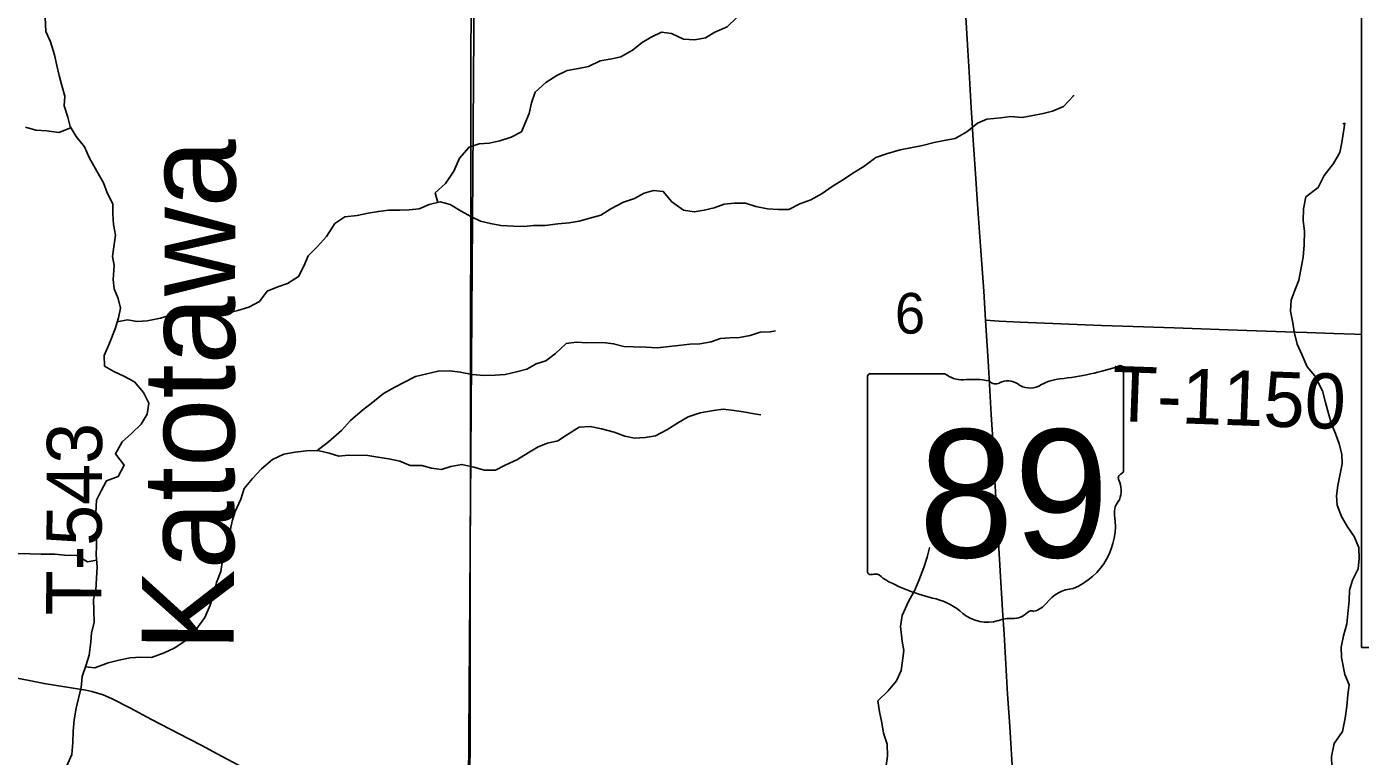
# Model space of a CAD drawing. Extents: x 0 to 34, y 0 to 22.
# Drawn here: x 2.753 to 4.127, y 15.888 to 16.64 of the extents above; entities that cross this region are included whole.
import ezdxf

# ---------------------------------------------------------------- set-up
doc = ezdxf.new("R2010")
doc.units = 0
for name, color, linetype in [('GM_X_Interstate_Route', 7, 'Continuous'), ('GM_X_Minor_River', 7, 'Continuous'), ('GM_X_Minor_River_Text', 7, 'Continuous'), ('GM_X_Section', 7, 'Continuous'), ('GM_X_Section_Text', 7, 'Continuous'), ('GM_X_State_Location', 7, 'Continuous'), ('GM_X_State_Route', 7, 'Continuous'), ('GM_X_State_Shield', 7, 'Continuous'), ('GM_X_Township_Road', 7, 'Continuous'), ('GM_X_Township_Road_Text', 7, 'Continuous')]:
    doc.layers.add(name, color=color, linetype=linetype)

msp = doc.modelspace()

# ---------------------------------------------------------------- linework, layer by layer
at = {"layer": 'GM_X_Interstate_Route'}
msp.add_lwpolyline([(2.1, 16.8784), (2.1, 14.1), (3.2011, 14.1), (3.2037, 14.7782), (3.2041, 14.9016), (3.2042, 14.9221), (3.2098, 15.7617), (3.2111, 16.7578), (3.2115, 16.8719), (3.0939, 16.8719), (2.6014, 16.878)], close=True, dxfattribs=at)
msp.add_lwpolyline([(4.6269, 16.8701), (3.6554, 16.8713), (3.6203, 16.8714), (3.2115, 16.8719), (3.2111, 16.7578), (3.2098, 15.7617), (3.2042, 14.9221), (3.2041, 14.9016), (3.2037, 14.7782), (3.2011, 14.1), (8.2568, 14.1)], dxfattribs=at)
at = {"layer": 'GM_X_Minor_River'}
for points in [[(2.7523, 16.7083), (2.7549, 16.6977), (2.7597, 16.6874), (2.7672, 16.6778), (2.7724, 16.6679), (2.7723, 16.6493), (2.7729, 16.6349), (2.7777, 16.6242), (2.7818, 16.6109), (2.7843, 16.5999)], [(3.1768, 16.4588), (3.174, 16.4686), (3.1847, 16.4783), (3.1931, 16.4908), (3.1989, 16.5044), (3.2089, 16.5157), (3.2191, 16.519), (3.2297, 16.52), (3.2407, 16.5222), (3.2521, 16.5259), (3.2628, 16.5314), (3.2709, 16.5503), (3.2732, 16.5613), (3.2771, 16.5723), (3.2878, 16.5824), (3.2992, 16.5895), (3.3099, 16.5947), (3.3216, 16.5969), (3.3319, 16.5987), (3.344, 16.6047), (3.3558, 16.6068), (3.3653, 16.609), (3.3771, 16.6157), (3.387, 16.6236), (3.3965, 16.6292), (3.4071, 16.6344), (3.4174, 16.6328), (3.4298, 16.627), (3.4415, 16.6265), (3.4525, 16.6283), (3.462, 16.6342), (3.4746, 16.6398), (3.4845, 16.6492)], [(2.7843, 16.5999), (2.7865, 16.5896), (2.7895, 16.5793), (2.7924, 16.5683), (2.7919, 16.5584), (2.7956, 16.5466), (2.7978, 16.5371), (2.8042, 16.5268), (2.8128, 16.5161), (2.8176, 16.505), (2.8254, 16.4909), (2.8322, 16.4791), (2.8362, 16.4688), (2.8418, 16.4574), (2.8417, 16.4471), (2.8424, 16.4361), (2.8446, 16.4251), (2.843, 16.413), (2.8414, 16.4031), (2.8432, 16.3936), (2.8423, 16.3792), (2.8434, 16.3697), (2.8474, 16.3598), (2.8496, 16.3499), (2.8476, 16.3397), (2.8441, 16.3283), (2.8383, 16.3136), (2.8329, 16.3011), (2.8332, 16.2901), (2.843, 16.2843), (2.8532, 16.2797), (2.8641, 16.2739), (2.8735, 16.2628), (2.8791, 16.2517), (2.8771, 16.2404), (2.871, 16.2302), (2.861, 16.2204), (2.8515, 16.2118), (2.8446, 16.1997), (2.8536, 16.1878), (2.8474, 16.1761), (2.8352, 16.1717), (2.8299, 16.1615), (2.8252, 16.1517), (2.8244, 16.1388), (2.8277, 16.1281), (2.8249, 16.1183), (2.8252, 16.1046), (2.8247, 16.0952), (2.8258, 16.083), (2.8249, 16.0713), (2.8244, 16.0591), (2.8221, 16.0493), (2.8224, 16.0379), (2.8226, 16.0257), (2.8199, 16.0151), (2.8191, 16.0057), (2.8174, 15.992), (2.8143, 15.9822), (2.8104, 15.9701), (2.8092, 15.9587), (2.8065, 15.9474), (2.8041, 15.9375), (2.8021, 15.9254), (2.8009, 15.9136), (2.8008, 15.9019), (2.7995, 15.8897), (2.7945, 15.878)], [(2.8464, 16.3357), (2.8571, 16.3377), (2.8669, 16.3361), (2.8772, 16.3367), (2.8908, 16.3393), (2.9014, 16.3426), (2.914, 16.3459), (2.9242, 16.345), (2.9363, 16.3457), (2.9465, 16.3456), (2.9579, 16.3443), (2.9708, 16.3472), (2.9818, 16.3509), (2.9928, 16.3565), (3.0009, 16.3674), (3.0119, 16.3719), (3.0217, 16.3752), (3.0332, 16.3823), (3.0386, 16.3932), (3.0432, 16.4038), (3.0527, 16.4132), (3.0619, 16.4237), (3.0704, 16.4369), (3.081, 16.444), (3.0935, 16.4451), (3.1049, 16.4476), (3.1155, 16.4494), (3.1258, 16.4508), (3.1375, 16.4507), (3.1473, 16.451), (3.1576, 16.452), (3.1678, 16.4565), (3.1792, 16.4594), (3.1894, 16.4567), (3.2007, 16.4497), (3.2105, 16.4443), (3.2207, 16.4393), (3.2309, 16.4369), (3.2415, 16.4349), (3.2547, 16.4344), (3.2657, 16.4339), (3.2752, 16.4349), (3.2873, 16.4348), (3.3002, 16.4366), (3.3119, 16.4376), (3.3222, 16.4394), (3.3332, 16.4424), (3.3446, 16.4457), (3.3549, 16.452), (3.3678, 16.4591), (3.3792, 16.4628), (3.3891, 16.4684), (3.3989, 16.4709), (3.4088, 16.4701), (3.4178, 16.4594), (3.4298, 16.4509), (3.4408, 16.4489), (3.451, 16.4507), (3.4613, 16.4532), (3.4715, 16.4569), (3.4818, 16.458), (3.4935, 16.4579), (3.5044, 16.4547), (3.5162, 16.4523), (3.5275, 16.4515), (3.5381, 16.4514), (3.5495, 16.4573), (3.5609, 16.4614), (3.5727, 16.4681), (3.583, 16.4752), (3.5944, 16.4823), (3.6043, 16.489), (3.6154, 16.4958), (3.6279, 16.5051), (3.639, 16.5088), (3.653, 16.5129), (3.6636, 16.515), (3.6761, 16.5176), (3.6879, 16.5205), (3.7, 16.523), (3.7095, 16.5248), (3.7217, 16.5315), (3.7327, 16.5405), (3.7423, 16.5446), (3.7567, 16.546), (3.7669, 16.5474), (3.7786, 16.5462), (3.7896, 16.5483), (3.8002, 16.5505), (3.8097, 16.5527), (3.8211, 16.5575), (3.8314, 16.5688), (3.8314, 16.5692)], [(2.7987, 16.5356), (2.7864, 16.5308), (2.7739, 16.5324), (2.7626, 16.5333), (2.752, 16.5364)], [(4.0975, 15.8764), (4.0972, 15.8877), (4.0999, 15.901), (4.1087, 15.9134), (4.1115, 15.9271), (4.1131, 15.9396), (4.114, 15.9513), (4.1156, 15.9616), (4.1111, 15.9722), (4.1075, 15.9897), (4.1072, 16.0003), (4.1096, 16.0121), (4.1131, 16.0242), (4.1156, 16.0484), (4.1157, 16.0591), (4.1188, 16.0693), (4.1246, 16.081), (4.1258, 16.0916), (4.1255, 16.103), (4.1207, 16.1144), (4.1139, 16.1244), (4.1076, 16.135), (4.1032, 16.1468), (4.1025, 16.1563), (4.1037, 16.167), (4.1061, 16.1791), (4.1081, 16.1893), (4.1078, 16.1992), (4.1052, 16.2098), (4.1015, 16.2205), (4.0974, 16.23), (4.0941, 16.241), (4.0912, 16.2525), (4.0879, 16.2646), (4.08, 16.2799), (4.0722, 16.2894), (4.067, 16.3013), (4.0618, 16.3127), (4.0588, 16.3252), (4.0574, 16.3347), (4.0549, 16.3465), (4.0557, 16.3579), (4.06, 16.3689), (4.0635, 16.3787), (4.0658, 16.3897), (4.0682, 16.4022), (4.0691, 16.4151), (4.0696, 16.4291), (4.0681, 16.4397), (4.0686, 16.4523), (4.071, 16.4644), (4.0836, 16.4741), (4.0898, 16.4866), (4.0993, 16.499), (4.1059, 16.5103), (4.1078, 16.5206), (4.111, 16.5403), (4.1091, 16.5399)], [(3.052, 16.2027), (3.0639, 16.212), (3.0773, 16.2236), (3.0868, 16.2338), (3.099, 16.2447), (3.1097, 16.2529), (3.1208, 16.2619), (3.1322, 16.2682), (3.1417, 16.2731), (3.1535, 16.2794), (3.1652, 16.282), (3.177, 16.2849), (3.1891, 16.2851), (3.1997, 16.2839), (3.2122, 16.2815), (3.2243, 16.2802), (3.2356, 16.2805), (3.2459, 16.2812), (3.2576, 16.2841), (3.2683, 16.287), (3.2778, 16.2922), (3.288, 16.2956), (3.2979, 16.3031), (3.309, 16.3132), (3.3196, 16.3146), (3.3302, 16.3141), (3.3465, 16.3143), (3.3578, 16.3131), (3.3684, 16.3103), (3.3783, 16.3099), (3.3908, 16.3094), (3.4025, 16.3089), (3.412, 16.3099), (3.4245, 16.3113), (3.4362, 16.3127), (3.4465, 16.313), (3.4582, 16.3152), (3.4677, 16.3185), (3.4776, 16.3191), (3.4874, 16.3194), (3.4984, 16.3216), (3.5087, 16.3249), (3.5189, 16.3252), (3.5246, 16.3263)], [(2.8136, 15.9799), (2.8234, 15.9791), (2.8371, 15.9842), (2.8481, 15.9868), (2.8598, 15.9893), (2.8708, 15.99), (2.8818, 15.9895), (2.8947, 15.9943), (2.905, 15.9991), (2.9172, 16.007), (2.9275, 16.0183), (2.9367, 16.0307), (2.9421, 16.0436), (2.9456, 16.0545), (2.9487, 16.067), (2.953, 16.0784), (2.955, 16.0901), (2.9585, 16.1037), (2.9616, 16.1155), (2.9648, 16.1302), (2.9679, 16.1401), (2.9737, 16.1529), (2.9772, 16.1639), (2.9856, 16.174), (2.9951, 16.1842), (3.0062, 16.1936), (3.018, 16.1992), (3.0297, 16.2013), (3.0441, 16.2031), (3.0544, 16.2026), (3.0646, 16.2002), (3.0748, 16.1971), (3.0842, 16.1981), (3.1047, 16.1979), (3.1149, 16.1963), (3.1262, 16.1943), (3.1376, 16.1919), (3.1481, 16.1876), (3.1603, 16.1875), (3.1701, 16.1848), (3.1803, 16.1835), (3.1902, 16.1865), (3.2015, 16.1886), (3.2136, 16.1859), (3.2246, 16.1827), (3.236, 16.1826), (3.2462, 16.1878), (3.258, 16.1934), (3.2698, 16.2005), (3.2801, 16.2068), (3.2896, 16.2106), (3.3002, 16.2131), (3.3101, 16.2195), (3.3223, 16.2269), (3.3336, 16.2276), (3.3454, 16.2252), (3.3582, 16.222), (3.3692, 16.2177), (3.3794, 16.2157), (3.3903, 16.2164), (3.401, 16.2182), (3.4124, 16.2242), (3.4246, 16.232), (3.4345, 16.2376), (3.447, 16.2417), (3.4606, 16.2442), (3.4705, 16.2456), (3.4818, 16.2443), (3.4917, 16.2427), (3.5026, 16.2407), (3.5094, 16.2399)], [(3.6385, 15.8782), (3.6398, 15.888), (3.6395, 15.9002), (3.6358, 15.9116), (3.634, 15.9222), (3.6318, 15.9336), (3.63, 15.945), (3.6407, 15.9552), (3.6491, 15.9657), (3.6538, 15.9763), (3.6553, 15.9861), (3.6566, 15.9968), (3.6551, 16.0063), (3.6534, 16.0215), (3.655, 16.0328), (3.6615, 16.0472), (3.6681, 16.0589), (3.6723, 16.0691), (3.6774, 16.0823), (3.6809, 16.0929), (3.6832, 16.1027), (3.6832, 16.1024)], [(2.8252, 16.09), (2.8156, 16.0884), (2.8047, 16.0946), (2.7922, 16.0951), (2.782, 16.096), (2.768, 16.0961), (2.7562, 16.0966), (2.7445, 16.0967)]]:
    msp.add_lwpolyline(points, dxfattribs=at)
at = {"layer": 'GM_X_Section'}
for points in [[(3.1023, 16.8785), (3.2153, 16.8759), (3.2082, 15.8593), (3.2075, 15.8525), (2.249, 15.8507), (2.253, 16.8782)], [(4.2148, 16.747), (4.2083, 16.8683), (4.1045, 16.8706), (3.2153, 16.8759), (3.2082, 15.8593), (4.2651, 15.8107), (4.2549, 16), (4.1282, 16), (4.1282, 16.747)]]:
    msp.add_lwpolyline(points, close=True, dxfattribs=at)
at = {"layer": 'GM_X_State_Route'}
msp.add_lwpolyline([(3.7693, 15.8618), (3.7655, 15.9238), (3.7635, 15.9517), (3.7615, 15.9889), (3.76, 16.0137), (3.7585, 16.0385), (3.7559, 16.0788), (3.7526, 16.1378), (3.7505, 16.1719), (3.7486, 16.2091), (3.7467, 16.2401), (3.7438, 16.2897), (3.7409, 16.3372), (3.7391, 16.3673), (3.7357, 16.4137), (3.7327, 16.4571), (3.7304, 16.4881), (3.7288, 16.5129), (3.7278, 16.5284), (3.727, 16.5408), (3.726, 16.5563), (3.7249, 16.5749), (3.7239, 16.5935), (3.7226, 16.6152), (3.7203, 16.6555)], dxfattribs=at)
at = {"layer": 'GM_X_State_Shield'}
for p, q in [((3.6991, 16.2822), (3.6219, 16.2822)), ((3.8829, 16.1825), (3.8829, 16.2872)), ((3.6193, 16.2788), (3.6193, 16.0786)), ((3.8829, 16.1825), (3.8829, 16.1825))]:
    msp.add_line(p, q, dxfattribs=at)
for centre, radius, start, end in [((3.6223, 16.2792), 0.00305, 98.1301, 188.1301), ((3.7175, 16.3054), 0.0296, 231.6195, 271.1119), ((3.789, 16.555), 0.2796, 275.8445, 288.9065), ((3.88, 16.2876), 0.00294, 351.8621, 97.738), ((3.7273, 16.1699), 0.1064, 80.4867, 94.9883), ((3.7514, 16.2802), 0.00855, 219.7921, 297.1024), ((3.764, 16.2571), 0.0178, 54.4667, 119.1411), ((3.7869, 16.2888), 0.0214, 233.8562, 294.8282), ((3.8247, 16.2211), 0.0563, 97.3462, 120.7689), ((3.8822, 16.1748), 0.00454, 107.944, 210.337), ((3.8533, 16.1616), 0.0273, 340.033, 23.6496), ((3.8798, 16.1821), 0.00314, 289.6038, 7.7341), ((3.8934, 16.1387), 0.0198, 136.8065, 186.9296), ((3.8047, 16.1254), 0.0699, 292.3089, 8.9858), ((3.6223, 16.0782), 0.00308, 171.9584, 258.3066), ((3.6228, 16.0987), 0.0235, 267.339, 280.6039), ((3.6276, 16.0671), 0.00848, 29.7484, 93.2717), ((3.7346, 16.2469), 0.2019, 240.4129, 257.1985), ((3.8342, 16.0225), 0.0383, 94.4031, 142.5768), ((3.6744, 15.9887), 0.0632, 47.1842, 75.836), ((3.7428, 16.0661), 0.0401, 230.7004, 286.2918), ((3.7689, 16.0511), 0.0214, 268.777, 315.5493), ((3.7882, 16.0317), 0.00601, 65.7517, 132.6484), ((3.7856, 16.0593), 0.0226, 282.8732, 323.2771), ((3.7659, 15.9969), 0.0329, 85.6951, 111.2099)]:
    msp.add_arc(centre, radius, start, end, dxfattribs=at)
at = {"layer": 'GM_X_Township_Road'}
for points in [[(3.7409, 16.3372), (3.755, 16.3365), (3.7767, 16.3354), (3.8605, 16.3319), (3.8823, 16.3311), (3.9351, 16.3295), (3.9909, 16.3275), (4.0099, 16.3268), (4.05, 16.3254), (4.0717, 16.3246), (4.0997, 16.3237), (4.1214, 16.3228), (4.1282, 16.3225)], [(2.7294, 15.9713), (2.7313, 15.9707), (2.771, 15.9627), (2.7925, 15.9593), (2.814, 15.9558), (2.8201, 15.9546), (2.8261, 15.953), (2.832, 15.951), (2.8405, 15.9473), (2.8599, 15.9374), (2.8818, 15.9257), (2.9011, 15.9157), (2.9203, 15.9057), (2.9341, 15.8985), (2.945, 15.8926), (2.9751, 15.8764), (3.0045, 15.8611)]]:
    msp.add_lwpolyline(points, dxfattribs=at)

# ---------------------------------------------------------------- texts
at = {"layer": 'GM_X_Minor_River_Text'}
msp.add_text('Katotawa', height=0.09474, rotation=89.7701, dxfattribs=at).set_placement((2.9663, 15.9957))
at = {"layer": 'GM_X_Section_Text'}
msp.add_text('6', height=0.0419, rotation=0, dxfattribs=at).set_placement((3.6475, 16.3235))
at = {"layer": 'GM_X_State_Location'}
for s in ['s', 'r']:
    msp.add_text(s, height=0.000189, dxfattribs=at).set_placement((3.7481, 16.1654))
msp.add_text('89', height=0.000189, rotation=0, dxfattribs=at).set_placement((3.7004, 16.1516))
at = {"layer": 'GM_X_State_Shield'}
msp.add_text('89', height=0.13184, dxfattribs=at).set_placement((3.6719, 16.0928))
at = {"layer": 'GM_X_Township_Road_Text'}
for s, rotation, p in [('T-1150', 357.944, (3.8704, 16.2336)), ('T-543', 89.7199, (2.8299, 16.0329))]:
    msp.add_text(s, height=0.05682, rotation=rotation, dxfattribs=at).set_placement(p)

doc.saveas('drawing.dxf')
